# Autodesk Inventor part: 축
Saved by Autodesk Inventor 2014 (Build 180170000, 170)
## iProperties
Created: 2026-07
Part Number: 축
Material: 강철, 탄소
Document SubType Name: Modeling
Designer: dg
Density: 7.87 g/cm^3
Appearance: 반연마
Mass: 200.03 g
Surface Area: 69.3424 cm^2
Volume: 25.4168 cm^3
Author: jhkim
Creation Date: 2026-07-02
Sending System: Autodesk Inventor 2027
Preprocessor: ST-DEVELOPER v20.1
Author: dg
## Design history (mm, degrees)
node "축1"
node "솔리드1"
node "기준1"
